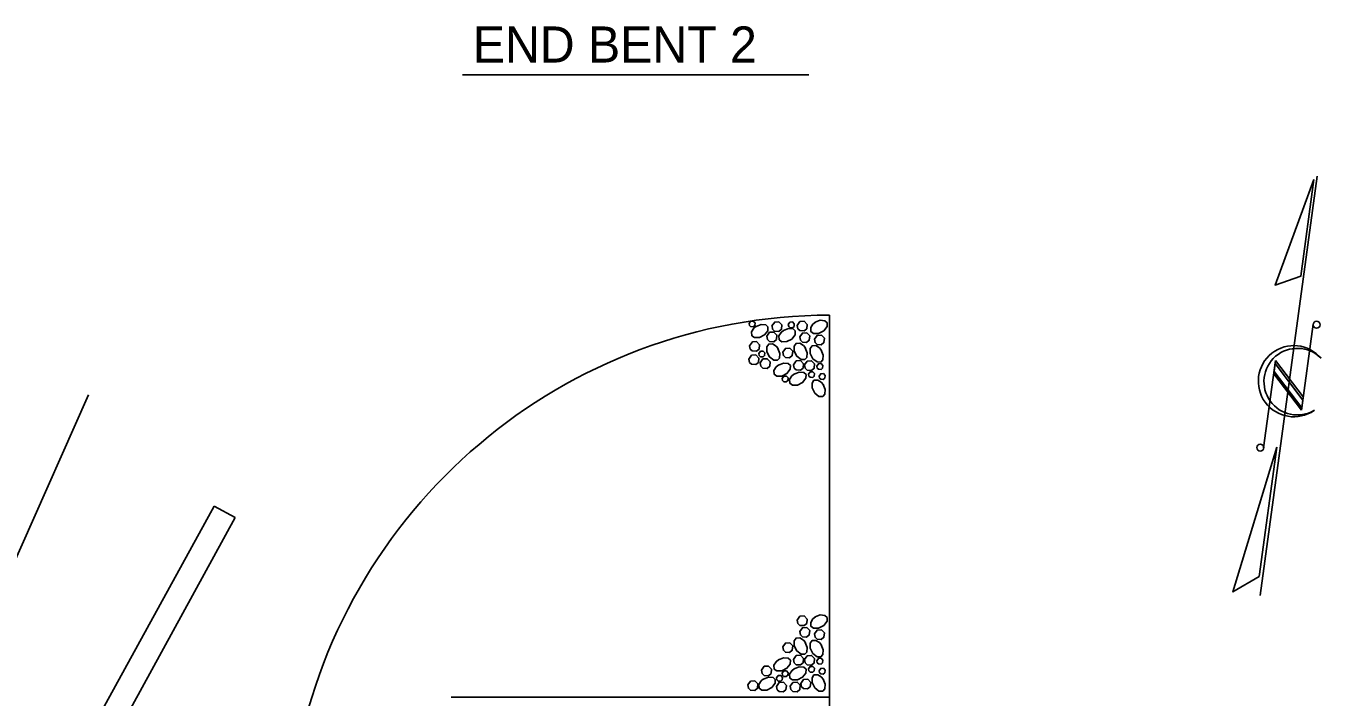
# Model space of a CAD drawing. Extents: x -20 to 509, y -659 to 21.
# Drawn here: x 139.4 to 193.2, y -86.1 to -58.2 of the extents above; entities that cross this region are included whole.
import ezdxf

# ---------------------------------------------------------------- set-up
doc = ezdxf.new("R2010")
doc.units = 0
for name, color, linetype in [('Default', 7, 'Continuous'), ('Exist Hydro Stream or Body of Water', 7, 'Continuous'), ('Exist Structure Major Bridge Seam', 7, 'Continuous'), ('Mis Object Lines', 7, 'Continuous'), ('Miscellaneous Lines CELL', 7, 'Continuous'), ('Sheet North Arrow CELL', 7, 'Continuous'), ('Sup Concrete Girder Lines', 7, 'Continuous'), ('Text', 7, 'Continuous')]:
    doc.layers.add(name, color=color, linetype=linetype)

msp = doc.modelspace()

# ---------------------------------------------------------------- linework, layer by layer
at = {"layer": 'Default'}
msp.add_line((161.608, -86.072), (171.608, -86.072), dxfattribs=at)
at = {"layer": 'Exist Hydro Stream or Body of Water'}
msp.add_lwpolyline([(133.79, -99.918), (134.208, -91.542), (136.321, -86.203), (141.964, -73.503)], dxfattribs=at)
at = {"layer": 'Exist Structure Major Bridge Seam'}
for p, q in [((141.463, -88.566), (147.188, -78.13)), ((147.188, -78.13), (148.065, -78.611)), ((141.492, -90.593), (148.065, -78.611))]:
    msp.add_line(p, q, dxfattribs=at)
at = {"layer": 'Mis Object Lines'}
for p in [(157.055, -86.072), (172.789, -87.072)]:
    msp.add_line(p, (172.789, -86.072), dxfattribs=at)
at = {"layer": 'Miscellaneous Lines CELL'}
for points in [[(169.446, -70.537), (169.513, -70.441), (169.621, -70.435), (169.695, -70.512), (169.685, -70.621), (169.618, -70.676), (169.512, -70.668), (169.462, -70.62), (169.446, -70.537)], [(169.737, -70.659), (169.946, -70.576), (170.139, -70.593), (170.23, -70.68), (170.227, -70.836), (170.088, -71.014), (169.874, -71.121), (169.672, -71.125), (169.558, -71.044), (169.547, -70.883), (169.639, -70.738), (169.745, -70.654)], [(170.4, -70.639), (170.512, -70.48), (170.691, -70.469), (170.816, -70.598), (170.798, -70.779), (170.687, -70.871), (170.511, -70.858), (170.427, -70.778), (170.401, -70.639)], [(171.08, -70.573), (171.148, -70.478), (171.255, -70.472), (171.329, -70.549), (171.319, -70.657), (171.252, -70.713), (171.146, -70.705), (171.097, -70.657), (171.08, -70.573)], [(171.447, -70.615), (171.56, -70.455), (171.738, -70.445), (171.863, -70.574), (171.845, -70.755), (171.734, -70.847), (171.558, -70.834), (171.475, -70.753), (171.448, -70.615)], [(172.199, -70.487), (172.409, -70.404), (172.601, -70.421), (172.693, -70.508), (172.69, -70.664), (172.551, -70.842), (172.337, -70.949), (172.134, -70.953), (172.02, -70.872), (172.01, -70.71), (172.102, -70.566), (172.208, -70.482)], [(170.19, -71.061), (170.302, -70.901), (170.481, -70.891), (170.605, -71.02), (170.587, -71.201), (170.476, -71.293), (170.3, -71.28), (170.217, -71.199), (170.19, -71.061)], [(170.875, -70.829), (171.085, -70.746), (171.277, -70.762), (171.369, -70.849), (171.366, -71.006), (171.227, -71.183), (171.013, -71.291), (170.81, -71.294), (170.696, -71.213), (170.686, -71.052), (170.778, -70.908), (170.884, -70.823)], [(171.553, -71.092), (171.665, -70.933), (171.844, -70.922), (171.968, -71.051), (171.95, -71.232), (171.84, -71.324), (171.663, -71.311), (171.58, -71.23), (171.553, -71.092)], [(172.165, -71.19), (172.278, -71.03), (172.456, -71.02), (172.581, -71.149), (172.563, -71.33), (172.452, -71.421), (172.276, -71.409), (172.193, -71.328), (172.166, -71.19)], [(169.471, -71.461), (169.583, -71.301), (169.762, -71.291), (169.886, -71.42), (169.868, -71.601), (169.758, -71.693), (169.581, -71.68), (169.498, -71.599), (169.471, -71.461)], [(170.647, -71.573), (170.73, -71.783), (170.714, -71.975), (170.627, -72.067), (170.471, -72.064), (170.293, -71.925), (170.186, -71.71), (170.182, -71.508), (170.263, -71.394), (170.424, -71.383), (170.568, -71.476), (170.653, -71.582)], [(170.849, -71.732), (170.961, -71.572), (171.14, -71.562), (171.264, -71.691), (171.246, -71.872), (171.135, -71.964), (170.959, -71.951), (170.876, -71.87), (170.849, -71.732)], [(171.786, -71.546), (171.869, -71.756), (171.853, -71.948), (171.766, -72.04), (171.609, -72.037), (171.432, -71.898), (171.324, -71.683), (171.321, -71.481), (171.402, -71.367), (171.563, -71.356), (171.707, -71.449), (171.791, -71.554)], [(172.45, -71.648), (172.533, -71.857), (172.517, -72.05), (172.43, -72.141), (172.274, -72.138), (172.096, -72), (171.989, -71.785), (171.985, -71.583), (172.066, -71.469), (172.227, -71.458), (172.371, -71.55), (172.456, -71.656)], [(169.44, -72.014), (169.552, -71.855), (169.731, -71.844), (169.855, -71.973), (169.837, -72.154), (169.727, -72.246), (169.55, -72.233), (169.467, -72.153), (169.44, -72.014)], [(169.856, -71.787), (169.923, -71.691), (170.031, -71.685), (170.105, -71.763), (170.094, -71.871), (170.028, -71.926), (169.922, -71.919), (169.872, -71.87), (169.856, -71.787)], [(169.913, -72.172), (170.025, -72.013), (170.204, -72.003), (170.328, -72.132), (170.31, -72.312), (170.2, -72.404), (170.023, -72.391), (169.94, -72.311), (169.913, -72.172)], [(170.672, -72.266), (170.882, -72.183), (171.074, -72.199), (171.166, -72.286), (171.163, -72.443), (171.024, -72.62), (170.809, -72.728), (170.607, -72.731), (170.493, -72.65), (170.482, -72.489), (170.575, -72.345), (170.68, -72.26)], [(171.297, -72.251), (171.409, -72.092), (171.588, -72.082), (171.712, -72.211), (171.694, -72.391), (171.584, -72.483), (171.407, -72.47), (171.324, -72.39), (171.297, -72.251)], [(171.758, -72.258), (171.87, -72.099), (172.049, -72.088), (172.173, -72.217), (172.155, -72.398), (172.045, -72.49), (171.868, -72.477), (171.785, -72.397), (171.758, -72.258)], [(170.823, -72.827), (170.89, -72.732), (170.997, -72.726), (171.072, -72.803), (171.061, -72.911), (170.995, -72.967), (170.889, -72.959), (170.839, -72.911), (170.823, -72.827)], [(171.322, -72.64), (171.532, -72.557), (171.724, -72.574), (171.816, -72.661), (171.813, -72.817), (171.674, -72.995), (171.46, -73.102), (171.257, -73.105), (171.143, -73.025), (171.133, -72.863), (171.225, -72.719), (171.331, -72.635)], [(171.921, -72.644), (171.988, -72.548), (172.096, -72.542), (172.17, -72.619), (172.159, -72.728), (172.093, -72.783), (171.987, -72.775), (171.937, -72.727), (171.921, -72.644)], [(172.268, -72.307), (172.335, -72.212), (172.442, -72.206), (172.517, -72.283), (172.506, -72.391), (172.44, -72.446), (172.334, -72.439), (172.284, -72.39), (172.268, -72.307)], [(172.362, -72.722), (172.43, -72.627), (172.537, -72.621), (172.611, -72.698), (172.601, -72.806), (172.534, -72.862), (172.428, -72.854), (172.379, -72.805), (172.362, -72.722)], [(172.532, -73.078), (172.615, -73.287), (172.598, -73.48), (172.511, -73.572), (172.355, -73.569), (172.177, -73.43), (172.07, -73.215), (172.066, -73.013), (172.147, -72.899), (172.308, -72.888), (172.453, -72.981), (172.537, -73.086)], [(171.447, -82.869), (171.56, -82.71), (171.738, -82.7), (171.863, -82.829), (171.845, -83.009), (171.734, -83.101), (171.558, -83.089), (171.475, -83.008), (171.448, -82.869)], [(172.199, -82.742), (172.409, -82.659), (172.601, -82.676), (172.693, -82.763), (172.69, -82.919), (172.551, -83.096), (172.337, -83.204), (172.134, -83.207), (172.02, -83.126), (172.01, -82.965), (172.102, -82.821), (172.208, -82.737)], [(171.553, -83.347), (171.665, -83.187), (171.844, -83.177), (171.968, -83.306), (171.95, -83.487), (171.84, -83.579), (171.663, -83.566), (171.58, -83.485), (171.553, -83.347)], [(172.165, -83.444), (172.278, -83.285), (172.456, -83.275), (172.581, -83.404), (172.563, -83.584), (172.452, -83.676), (172.276, -83.663), (172.193, -83.583), (172.166, -83.444)], [(170.849, -83.986), (170.961, -83.827), (171.14, -83.817), (171.264, -83.946), (171.246, -84.126), (171.135, -84.218), (170.959, -84.206), (170.876, -84.125), (170.849, -83.986)], [(171.786, -83.801), (171.869, -84.01), (171.853, -84.203), (171.766, -84.294), (171.609, -84.291), (171.432, -84.153), (171.324, -83.938), (171.321, -83.736), (171.402, -83.622), (171.563, -83.611), (171.707, -83.703), (171.791, -83.809)], [(172.45, -83.902), (172.533, -84.112), (172.517, -84.304), (172.43, -84.396), (172.274, -84.393), (172.096, -84.254), (171.989, -84.04), (171.985, -83.837), (172.066, -83.723), (172.227, -83.713), (172.371, -83.805), (172.456, -83.911)], [(170.672, -84.521), (170.882, -84.437), (171.074, -84.454), (171.166, -84.541), (171.163, -84.697), (171.024, -84.875), (170.809, -84.982), (170.607, -84.986), (170.493, -84.905), (170.482, -84.744), (170.575, -84.6), (170.68, -84.515)], [(171.297, -84.506), (171.409, -84.347), (171.588, -84.336), (171.712, -84.465), (171.694, -84.646), (171.584, -84.738), (171.407, -84.725), (171.324, -84.644), (171.297, -84.506)], [(171.758, -84.513), (171.87, -84.353), (172.049, -84.343), (172.173, -84.472), (172.155, -84.653), (172.045, -84.745), (171.868, -84.732), (171.785, -84.651), (171.758, -84.513)], [(172.268, -84.562), (172.335, -84.466), (172.442, -84.46), (172.517, -84.538), (172.506, -84.646), (172.44, -84.701), (172.334, -84.693), (172.284, -84.645), (172.268, -84.562)], [(169.963, -84.951), (170.075, -84.792), (170.254, -84.782), (170.378, -84.911), (170.36, -85.091), (170.25, -85.183), (170.073, -85.171), (169.99, -85.09), (169.963, -84.951)], [(170.823, -85.082), (170.89, -84.986), (170.997, -84.98), (171.072, -85.058), (171.061, -85.166), (170.995, -85.221), (170.889, -85.214), (170.839, -85.165), (170.823, -85.082)], [(171.322, -84.895), (171.532, -84.812), (171.724, -84.829), (171.816, -84.916), (171.813, -85.072), (171.674, -85.249), (171.46, -85.357), (171.257, -85.36), (171.143, -85.279), (171.133, -85.118), (171.225, -84.974), (171.331, -84.89)], [(171.921, -84.898), (171.988, -84.803), (172.096, -84.796), (172.17, -84.874), (172.159, -84.982), (172.093, -85.037), (171.987, -85.03), (171.937, -84.981), (171.921, -84.898)], [(172.362, -84.977), (172.43, -84.881), (172.537, -84.875), (172.611, -84.953), (172.601, -85.061), (172.534, -85.116), (172.428, -85.109), (172.379, -85.06), (172.362, -84.977)], [(169.395, -85.568), (169.507, -85.408), (169.686, -85.398), (169.81, -85.527), (169.792, -85.708), (169.682, -85.8), (169.505, -85.787), (169.422, -85.706), (169.395, -85.568)], [(170.041, -85.322), (170.251, -85.239), (170.443, -85.255), (170.535, -85.343), (170.532, -85.499), (170.393, -85.676), (170.179, -85.784), (169.976, -85.787), (169.862, -85.706), (169.852, -85.545), (169.944, -85.401), (170.05, -85.317)], [(170.584, -85.627), (170.696, -85.467), (170.875, -85.457), (170.999, -85.586), (170.981, -85.767), (170.871, -85.859), (170.694, -85.846), (170.611, -85.765), (170.584, -85.627)], [(170.592, -85.277), (170.659, -85.181), (170.766, -85.175), (170.841, -85.252), (170.83, -85.361), (170.764, -85.416), (170.658, -85.408), (170.608, -85.36), (170.592, -85.277)], [(171.162, -85.62), (171.274, -85.461), (171.453, -85.451), (171.578, -85.58), (171.56, -85.76), (171.449, -85.852), (171.272, -85.839), (171.189, -85.759), (171.162, -85.62)], [(171.597, -85.503), (171.709, -85.344), (171.888, -85.334), (172.012, -85.463), (171.994, -85.643), (171.884, -85.735), (171.707, -85.722), (171.624, -85.642), (171.597, -85.503)], [(172.532, -85.333), (172.615, -85.542), (172.598, -85.735), (172.511, -85.826), (172.355, -85.823), (172.177, -85.684), (172.07, -85.47), (172.066, -85.268), (172.147, -85.154), (172.308, -85.143), (172.453, -85.235), (172.537, -85.341)]]:
    msp.add_lwpolyline(points, dxfattribs=at)
at = {"layer": 'Sheet North Arrow CELL'}
for p, q in [((190.705, -81.851), (193.087, -64.409)), ((192.916, -70.568), (192.427, -74.148)), ((191.351, -72.074), (190.854, -75.713)), ((192.503, -73.59), (191.351, -72.074)), ((193.227, -71.969), (193.244, -71.985)), ((192.427, -74.148), (191.275, -72.632)), ((191.333, -72.206), (191.289, -72.533)), ((192.44, -74.049), (191.289, -72.533)), ((191.289, -72.533), (192.44, -74.049)), ((192.485, -73.721), (191.333, -72.206)), ((192.44, -74.049), (192.485, -73.721))]:
    msp.add_line(p, q, dxfattribs=at)
for points in [[(192.945, -64.545), (191.331, -68.939), (192.396, -68.57)], [(191.402, -75.686), (189.575, -81.697), (190.669, -81.053)]]:
    msp.add_lwpolyline(points, close=True, dxfattribs=at)
for centre in [(193.057, -70.59), (190.712, -75.699)]:
    msp.add_circle(centre, 0.144, dxfattribs=at)
for centre, radius, start, end in [((192.111, -72.937), 1.479, 40.0635, 304.6175), ((192.253, -72.956), 1.386, 45.3185, 300.8522)]:
    msp.add_arc(centre, radius, start, end, dxfattribs=at)
at = {"layer": 'Sup Concrete Girder Lines'}
for p, q in [((172.789, -86.072), (172.789, -70.188)), ((172.789, -86.072), (172.789, -70.188)), ((161.608, -86.072), (172.789, -86.072))]:
    msp.add_line(p, q, dxfattribs=at)
msp.add_arc((172.847, -92.8), 22.612, 90.1461, 170.5127, dxfattribs=at)
at = {"layer": 'Text'}
msp.add_line((157.522, -60.193), (171.933, -60.193), dxfattribs=at)

# ---------------------------------------------------------------- texts
msp.add_text('END BENT 2', height=1.5, dxfattribs=at).set_placement((157.955, -59.685))

doc.saveas('drawing.dxf')
